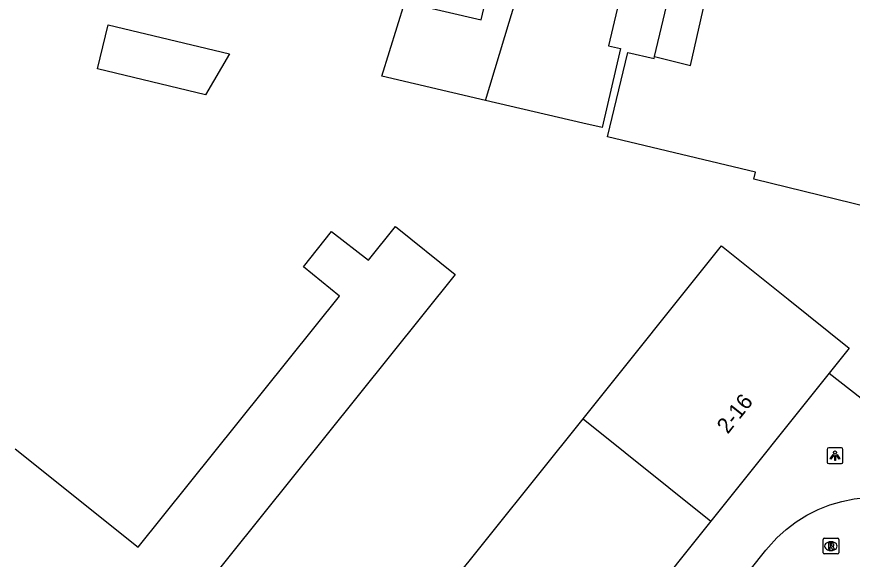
# Model space of a CAD drawing. Extents: x 159888 to 160757, y 384031 to 384746.
# Drawn here: x 160256.1 to 160309.4, y 384409 to 384443.7 of the extents above; entities that cross this region are included whole.
import ezdxf

# ---------------------------------------------------------------- set-up
doc = ezdxf.new("R2010")
doc.units = 0
for name, color, linetype in [('IMGEO_Lichtpunt', 7, 'Continuous'), ('IMGEO_Pand', 7, 'Continuous'), ('IMGEO_Pand_nummerreeks', 7, 'Continuous'), ('IMGEO_Rijbaan_lokaal_open', 7, 'Continuous'), ('IMGEO_Rioolput', 7, 'Continuous'), ('IMGEO_Voetpad_open', 7, 'Continuous')]:
    doc.layers.add(name, color=color, linetype=linetype)

msp = doc.modelspace()

# ---------------------------------------------------------------- linework, layer by layer
at = {"layer": 'IMGEO_Lichtpunt'}
for p, q in [((160308.725, 384416.132), (160307.917, 384416.132)), ((160308.725, 384416.132), (160307.917, 384416.132)), ((160307.823, 384416.037), (160307.823, 384415.23)), ((160307.823, 384416.037), (160307.823, 384415.23)), ((160308.819, 384415.23), (160308.819, 384416.037)), ((160308.819, 384415.23), (160308.819, 384416.037)), ((160307.917, 384415.136), (160308.725, 384415.136)), ((160307.917, 384415.136), (160308.725, 384415.136))]:
    msp.add_line(p, q, dxfattribs=at)
for points in [[(160308.197, 384415.701), (160308.236, 384415.673), (160308.048, 384415.411), (160308.01, 384415.438), (160308.197, 384415.701)], [(160308.299, 384415.653), (160308.346, 384415.653), (160308.346, 384415.331), (160308.299, 384415.331), (160308.299, 384415.653)], [(160308.409, 384415.673), (160308.447, 384415.7), (160308.634, 384415.438), (160308.595, 384415.41), (160308.409, 384415.673)]]:
    msp.add_lwpolyline(points, dxfattribs=at)
msp.add_circle((160308.322, 384415.835), 0.0994, dxfattribs=at)
for centre, start, end in [((160307.917, 384416.037), 90, 180), ((160307.917, 384416.037), 90, 180), ((160308.725, 384416.037), 0, 90), ((160308.725, 384416.037), 0, 90), ((160307.917, 384415.23), 180, 270), ((160307.917, 384415.23), 180, 270), ((160308.725, 384415.23), 270, 0), ((160308.725, 384415.23), 270, 360)]:
    msp.add_arc(centre, 0.0946, start, end, dxfattribs=at)
at = {"layer": 'IMGEO_Pand'}
for points in [[(160286.008, 384438.319), (160279.38, 384439.867), (160280.848, 384444.592), (160285.73, 384443.452), (160288.124, 384453.699), (160285.639, 384454.28), (160286.408, 384457.571), (160287.563, 384462.407)], [(160286.008, 384438.319), (160287.524, 384443.321), (160288.815, 384447.582), (160292.435, 384461.224)], [(160297.597, 384459.97), (160296.422, 384455.14), (160295.674, 384451.94), (160295.87, 384450.381), (160293.867, 384441.801), (160294.621, 384441.627), (160293.458, 384436.58), (160292.227, 384436.867), (160286.008, 384438.319)], [(160296.797, 384441.121), (160299.123, 384450.862), (160296.676, 384451.446), (160297.495, 384454.874), (160298.67, 384459.715)], [(160296.797, 384441.121), (160299.093, 384440.541), (160300.153, 384445.262)], [(160261.244, 384440.326), (160261.924, 384443.152), (160269.667, 384441.288), (160268.123, 384438.67), (160261.244, 384440.326)], [(160326.814, 384439.294), (160324.076, 384428.151), (160303.139, 384433.295), (160303.247, 384433.733), (160293.798, 384435.989), (160295.086, 384441.385), (160296.764, 384440.984), (160296.797, 384441.121)], [(160255.98, 384416.079), (160263.825, 384409.786), (160276.686, 384425.818), (160274.378, 384427.7), (160276.166, 384429.952), (160278.536, 384428.125), (160280.249, 384430.26), (160284.068, 384427.196), (160263.423, 384401.459)], [(160292.235, 384417.992), (160301.062, 384429.026), (160305.325, 384425.616), (160309.229, 384422.492), (160307.955, 384420.899)], [(160307.955, 384420.899), (160300.402, 384411.459)], [(160283.407, 384406.959), (160292.235, 384417.992)], [(160292.235, 384417.992), (160300.402, 384411.459)], [(160300.402, 384411.459), (160291.575, 384400.426)]]:
    msp.add_lwpolyline(points, dxfattribs=at)
at = {"layer": 'IMGEO_Rijbaan_lokaal_open'}
msp.add_lwpolyline([(160258.945, 384353.29), (160260.04, 384354.657), (160262.944, 384358.346), (160266.78, 384363.051), (160279.413, 384378.913), (160290.673, 384392.988), (160303.911, 384409.606), (160304.069, 384409.799), (160304.613, 384410.388), (160305.206, 384410.925), (160305.846, 384411.408), (160306.526, 384411.831), (160307.241, 384412.192), (160307.985, 384412.487), (160308.753, 384412.715), (160309.538, 384412.874), (160310.334, 384412.961), (160311.135, 384412.977), (160311.934, 384412.922)], dxfattribs=at)
at = {"layer": 'IMGEO_Rioolput'}
for p, q in [((160307.557, 384409.432), (160307.557, 384410.284)), ((160307.632, 384410.358), (160308.484, 384410.358)), ((160308.558, 384410.284), (160308.558, 384409.432)), ((160308.045, 384410.138), (160308.07, 384410.138)), ((160308.484, 384409.358), (160307.632, 384409.358)), ((160308.068, 384409.578), (160308.043, 384409.578))]:
    msp.add_line(p, q, dxfattribs=at)
for points in [[(160307.557, 384409.432), (160307.557, 384410.284)], [(160307.632, 384410.358), (160308.484, 384410.358)], [(160308.558, 384410.284), (160308.558, 384409.432)], [(160308.146, 384410.056), (160307.894, 384410.058), (160307.894, 384409.658)], [(160307.894, 384409.658), (160308.018, 384409.658), (160308.018, 384409.82), (160308.029, 384409.82)], [(160308.072, 384409.977), (160308.018, 384409.977), (160308.018, 384409.896)], [(160308.018, 384409.896), (160308.07, 384409.896)], [(160308.076, 384409.791), (160308.147, 384409.658), (160308.287, 384409.658), (160308.222, 384409.784)], [(160308.484, 384409.358), (160307.632, 384409.358)]]:
    msp.add_lwpolyline(points, dxfattribs=at)
for centre, radius, start, end in [((160307.634, 384410.282), 0.0765, 91.552, 178.448), ((160307.634, 384410.282), 0.0765, 91.552, 178.448), ((160308.482, 384410.282), 0.0765, 1.552, 88.448), ((160308.482, 384410.282), 0.0765, 1.552, 88.448), ((160308.028, 384409.767), 0.0533, 26.0293, 88.6989), ((160308.054, 384410.085), 0.19, 274.7715, 282.9687), ((160308.078, 384409.881), 0.0964, 77.0061, 93.1865), ((160308.092, 384409.938), 0.0378, 276.6634, 79.6772), ((160308.145, 384409.946), 0.109, 350.3612, 89.416), ((160308.143, 384409.946), 0.112, 277.5842, 350.9817), ((160308.127, 384409.731), 0.108, 29.5134, 73.7905), ((160307.634, 384409.434), 0.0765, 181.552, 268.448), ((160307.634, 384409.434), 0.0765, 181.552, 268.448), ((160308.482, 384409.434), 0.0765, 271.552, 358.448), ((160308.482, 384409.434), 0.0765, 271.552, 358.448)]:
    msp.add_arc(centre, radius, start, end, dxfattribs=at)
for centre, major_axis, ratio, start_param, end_param in [((160308.044, 384409.858), (-0.387, 0.002), 0.722429, 4.712389, 7.853982), ((160308.069, 384409.858), (-0.39, 0.002), 0.717154, 1.570796, 4.712389)]:
    msp.add_ellipse(centre, major_axis=major_axis, ratio=ratio, start_param=start_param, end_param=end_param, dxfattribs=at)
at = {"layer": 'IMGEO_Voetpad_open'}
msp.add_lwpolyline([(160307.955, 384420.899), (160335.895, 384399.076)], dxfattribs=at)

# ---------------------------------------------------------------- texts
at = {"layer": 'IMGEO_Pand_nummerreeks'}
msp.add_text('2-16', height=1, rotation=51.534, dxfattribs=at).set_placement((160301.471, 384416.971))

doc.saveas('drawing.dxf')
